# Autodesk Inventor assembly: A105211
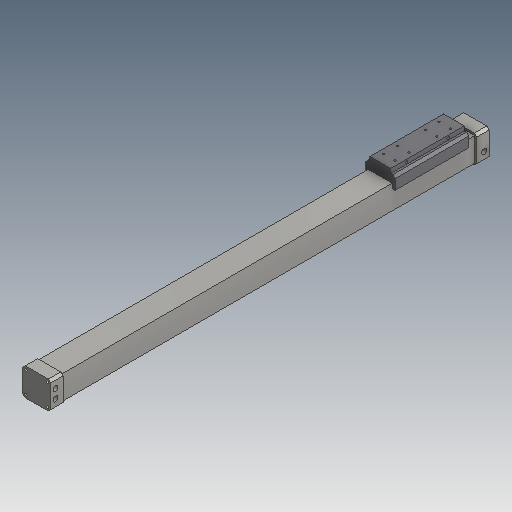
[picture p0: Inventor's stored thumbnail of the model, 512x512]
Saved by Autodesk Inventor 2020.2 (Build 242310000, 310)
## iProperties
Created: 1999-09
Part Number: A105211
Document SubType Name: Assembly
Designer: Autodesk
Mass: 9090.7 g
Surface Area: 2523.16 cm^2
Volume: 2863.63 cm^3
Density: 3.17454 g/cm^3
Control State: 0
Master: False
Checked Out: False
Shininess: 0.0
Length Units: 11269
Angle Units: 11279
Time Units: 11290
Mass Units: 11286
Length Display Precision: 3
Angle Display Precision: 2
Compacted: True
Dimensions: 82x952,3x64 mm
Mass: 20,042 lb
DocNumber: A105211.iam
Folder: 01 - Themengebiete\Simplification\01 - Packaging machine\
VDS_Category: 3D Komponenten
Density: 0.0
Volumn: 0.0
Area: 0.0
PropertySet Name: Model Information
Author: Autodesk
Revision Number: -
Title: linear unit
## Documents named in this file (3)
- D:\07 - DEMODATEN\OTX 2019 - Dataset - UPDATE - Dez2019\Designs\07-Packing machine\A105211.iam
- D:\07 - DEMODATEN\OTX 2019 - Dataset - UPDATE - Dez2019\Designs\07-Packing machine\Parts\ADSK-011813.ipt
- D:\07 - DEMODATEN\OTX 2019 - Dataset - UPDATE - Dez2019\Designs\07-Packing machine\Parts\ADSK-011814.ipt
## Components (2 placed, 2 different names)
1. A105211-001 — Flush:1, Flush:2, STROKE, Fluchtend:4, Fluchtend:5, Fluchtend:6
2. A105211-002 — Flush:1, Flush:2, STROKE
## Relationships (6: Flush 6)
- Flush:1: A105211-001 ↔ A105211-002
- Flush:2: A105211-001 ↔ A105211-002
- STROKE [Flush]: A105211-001 ↔ A105211-002
- Fluchtend:4 [Flush]: A105211-001
- Fluchtend:5 [Flush]: A105211-001
- Fluchtend:6 [Flush]: A105211-001
